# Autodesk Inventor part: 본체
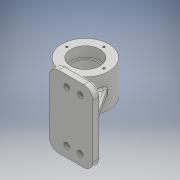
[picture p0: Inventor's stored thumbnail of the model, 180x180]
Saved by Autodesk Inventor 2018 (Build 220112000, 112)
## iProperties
Created: 2023-08
Part Number: 본체
Material: 일반
Document SubType Name: Modeling
Designer: home
Density: 1 g/cm^3
Appearance: 기본값
Mass: 285.547 g
Surface Area: 534.467 cm^2
Volume: 285.547 cm^3
Author: home
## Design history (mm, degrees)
sketch "스케치1"
  geometry: C1 r 38 at (0, 0); 1 further point
  constraints: 1 centre point, 1 coincident
  dimensions: "d0" = 76 diameter of C1
extrude "돌출1" new body sketch "스케치1" stored distance "d1" = 54; taper "d2" = 0 deg
node "작업 평면1"
sketch "스케치2"
  geometry: L1 (0, 0)-(-12, 0); L2 (-12, 0)-(-12, -58); L3 (-12, -58)-(-82, -58); L4 (-82, -58)-(-82, 58); L5 (-82, 58)-(-12, 58); L6 (-12, 58)-(-12, -58)
  constraints: 12 end point, 2 horizontal, 2 parallel, 2 perpendicular
  dimensions: "d4" = 12 distance of L1.start L1.end; "d5" = 58 distance of L1.end L2.end; "d6" = 70 distance of L4.end L5.end; "d7" = 116 distance of L3.end L4.end
extrude "돌출2" join sketch "스케치2" distance "d8" = 12; taper "d9" = 0 deg
sketch "스케치3"
  geometry: L1 (116, 0)-(0, 0) reference; L2 (116, 0)-(116, 12) reference; L3 (0, 12)-(116, 12) reference; L4 (0, 0)-(0, 12) reference; L5 (0, 12)-(22, 12); L6 (22, 12)-(41.062, 41.353); L7 (116, 12)-(94, 12); L8 (94, 12)-(74.938, 41.353); L9 (94, 12)-(129, 12); L10 (41.062, 41.353)-(74.938, 41.353); L11 (22, 12)-(94, 12); 1 further point
  constraints: 14 end point, 2 point on line, 1 collinear, 1 equal length, 1 horizontal
  dimensions: "d10" = 22 distance of L3.start L5.end; "d11" = 35 distance of L5.end L6.end; "d12" = 123 deg angle of L6 L5; "d13" = 22 distance of L2.end L7.end; "d14" = 35 distance of L7.end L8.end; "d15" = 123 deg angle of L9 L8
extrude "돌출3" join sketch "스케치3" distance "d16" = 8; taper "d17" = 0 deg
sketch "스케치4"
  geometry: L1 (12, -70)-(82, -70) reference; L2 (12, -70)-(12, -58) reference; L3 (82, -58)-(12, -58) reference; L4 (82, -70)-(82, -58) reference; L5 (12, -58)-(74, -58); L6 (74, -58)-(36.334, 0); L7 (74, -58)-(143.157, -58); 1 further point
  constraints: 6 end point, 1 equal length, 1 horizontal, 1 point on line
  dimensions: "d18" = 62 distance of L2.end L5.end; "d19" = 123 deg angle of L7 L6
feature "리브1" sketch "스케치4" dims "d20" = 1, "d21" = 12, "d22" = 0, "d23" = 0, "d24" = 1, "d25" = 1
sketch "스케치5" dims "d36" = 10
  geometry: L1 (0, 0)-(40, 0); L2 (40, 0)-(40, -41); L3 (40, -41)-(62, -41); L4 (40, -41)-(62, -41); L5 (40, -51)-(62, -51); L6 (62, -31)-(40, -31); L7 (62, 51)-(40, 51); L8 (40, 31)-(62, 31); A1 r 10 centre (40, -41) between (40, -31) and (40, -51); A2 r 10 centre (62, -41) between (62, -51) and (62, -31); A3 r 10 centre (62, 41) between (62, 31) and (62, 51); A4 r 10 centre (40, 41) between (40, 51) and (40, 31); 1 further point
  constraints: 18 end point, 8 point on circle, 4 centre point, 4 tangent, 3 horizontal, 1 midpoint, 1 parallel, 1 perpendicular, 1 vertical, 10 other
  dimensions: "d26" = 40 distance of L1.start L1.end; "d27" = 41 distance of L1.end L2.end; "d28" = 22 distance of L2.end L3.end; "d30" = 20 diameter of A2; "d33" = 82 distance of L6.start L7.start
extrude "돌출4" join sketch "스케치5" distance "d38" = 3; taper "d39" = 0 deg
sketch "스케치6"
  geometry: L1 (62, 51)-(40, 51) reference; L2 (40, 31)-(62, 31) reference; L3 (40, -51)-(62, -51) reference; L4 (62, -31)-(40, -31) reference; A1 r 10 centre (40, 41) between (40, 51) and (40, 31) reference; A2 r 10 centre (62, 41) between (62, 31) and (62, 51) reference; A3 r 10 centre (62, -41) between (62, -51) and (62, -31) reference; A4 r 10 centre (40, -41) between (40, -31) and (40, -51) reference; 5 further points
  constraints: 4 coincident
hole "구멍1" sketch "스케치6" at (62, 41), (40, 41), (62, -41), (40, -41) diameter "d40" = 9; stored, may be unused: countersink angle "d44" = 90 deg, drill point angle "d46" = 118 deg; dims "d41" = 6, "d42" = 4, "d43" = 2, "d45" = 8
sketch "스케치7"
  geometry: C1 r 23.5 at (0, 0); 1 further point
  constraints: 1 centre point, 1 coincident
  dimensions: "d47" = 47 diameter of C1
extrude "돌출5" cut sketch "스케치7" distance "d48" = 17; taper "d49" = 0 deg
sketch "스케치8"
  geometry: C1 r 20.5 at (0, 0); 1 further point
  constraints: 1 centre point, 1 coincident
  dimensions: "d50" = 41 diameter of C1
extrude "돌출6" cut sketch "스케치8" stored distance "d51" = 17; taper "d52" = 0 deg
sketch "스케치9" dims "d53" = 60
  geometry: L1 (0, 0)-(0, 30); 4 further points
  constraints: 2 end point, 1 coincident, 1 vertical, 1 vertical alignment, 7 other
  dimensions: "d56" = 360 deg dimension on point (0, 0) L1.end (derived)
hole "구멍2" sketch "스케치9" at (0, 30), (-30, 0), (0, -30), (30, 0) diameter "d58" = 3.242; stored, may be unused: countersink angle "d62" = 90 deg, drill point angle "d64" = 118 deg; dims "d59" = 8, "d60" = 4, "d61" = 2, "d63" = 10
node "작업 평면2"
sketch "스케치10"
  geometry: C1 r 8 at (0, 0); 1 further point
  constraints: 1 centre point, 1 coincident
  dimensions: "d66" = 16 diameter of C1
extrude "돌출7" join sketch "스케치10" stored distance "d67" = 17; taper "d68" = 0 deg
hole "구멍3" diameter "d71" = 5.188; stored, may be unused: countersink angle "d75" = 90 deg, drill point angle "d77" = 118 deg; dims "d72" = 22, "d73" = 7, "d74" = 4, "d76" = 26, "d78" = 10, "d79" = 10
fillet "모깎기1" dims "d80" = 1, "d81" = 3
fillet "모깎기2" dims "d82" = 3, "d86" = 15
sketch "스케치11"
  geometry: L1 (37.266, 30)-(78.734, 30) reference; L2 (23.629, 9)-(37.266, 30) reference; L3 (15, 9)-(23.629, 9) reference; L4 (101, 0)-(15, 0) reference; L5 (92.371, 9)-(101, 9) reference; L6 (78.734, 30)-(92.371, 9) reference; L7 (58, 0)-(58, 19); L8 (15, 0)-(15, 9) reference; L9 (101, 9)-(101, 0) reference; 2 further points
  constraints: 2 end point, 1 coincident, 1 midpoint, 1 vertical, 1 other
  dimensions: "d83" = 19 distance of L7.start L7.end
feature "엠보싱1" sketch "스케치11" dims "d10" = 22, "d11" = 35, "d12" = 123 deg, "d13" = 22, "d14" = 35, "d15" = 123 deg, "d84" = 0.5, "d85" = 0
node "솔리드1"
mirror "미러1"
mirror "미러2"
node "투영된 루프1"
node "투영된 루프2"
node "투영된 루프3"
node "투영된 루프4"
node "투영된 루프5"
other parameters: "d65" = -111
